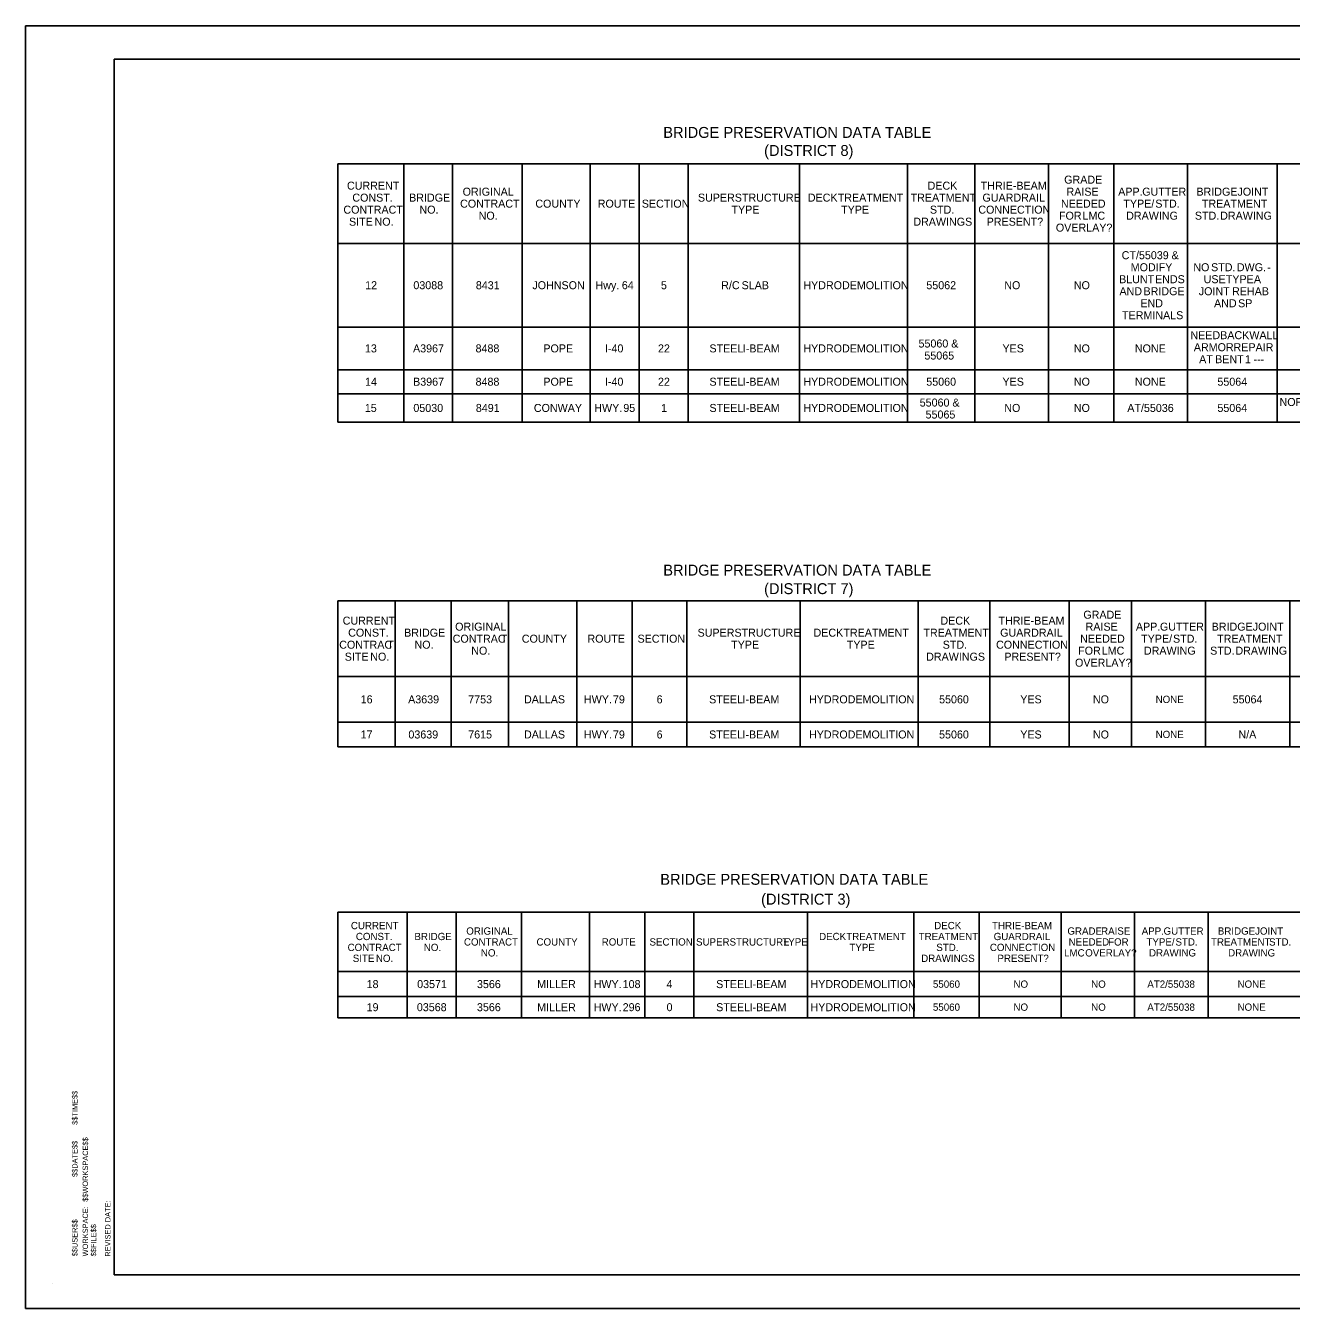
# Model space of a CAD drawing. Extents: x 16 to 1228740, y 11 to 152440.
# Drawn here: x 15.657 to 17.466, y 10.709 to 12.543 of the extents above; entities that cross this region are included whole.
import ezdxf

# ---------------------------------------------------------------- set-up
doc = ezdxf.new("R2010")
doc.units = 0
doc.layers.add('B_Text', color=7, linetype='Continuous')
doc.layers.add('R_Border', color=7, linetype='Continuous')

msp = doc.modelspace()

# ---------------------------------------------------------------- linework, layer by layer
at = {"layer": 'B_Text'}
for p, q in [((16.103, 12.3452), (16.103, 12.3452)), ((16.103, 12.3452), (17.5915, 12.3452)), ((16.103, 11.9761), (16.103, 12.3452)), ((16.1973, 11.9761), (16.1973, 12.3452)), ((16.2672, 11.9761), (16.2672, 12.3452)), ((16.3666, 11.9761), (16.3666, 12.3452)), ((16.4639, 11.9761), (16.4639, 12.3452)), ((16.5339, 11.9761), (16.5339, 12.3452)), ((16.6039, 11.9761), (16.6039, 12.3452)), ((16.7631, 11.9761), (16.7631, 12.3452)), ((16.9172, 11.9761), (16.9172, 12.3452)), ((17.0135, 11.9761), (17.0135, 12.3452)), ((17.119, 11.9761), (17.119, 12.3452)), ((17.2123, 11.9761), (17.2123, 12.3452)), ((17.3177, 11.9761), (17.3177, 12.3452)), ((17.4455, 11.9761), (17.4455, 12.3452)), ((16.103, 12.2316), (17.5915, 12.2316)), ((16.103, 12.112), (17.5915, 12.112)), ((16.103, 12.0511), (17.5915, 12.0511)), ((16.103, 12.0167), (17.5915, 12.0167)), ((16.103, 11.9761), (17.5915, 11.9761)), ((16.103, 11.7209), (16.103, 11.7209)), ((16.103, 11.7209), (17.6037, 11.7209)), ((16.103, 11.512), (16.103, 11.7209)), ((16.1851, 11.512), (16.1851, 11.7209)), ((16.2652, 11.512), (16.2652, 11.7209)), ((16.3473, 11.512), (16.3473, 11.7209)), ((16.4447, 11.512), (16.4447, 11.7209)), ((16.5238, 11.512), (16.5238, 11.7209)), ((16.6018, 11.512), (16.6018, 11.7209)), ((16.7641, 11.512), (16.7641, 11.7209)), ((16.9324, 11.512), (16.9324, 11.7209)), ((17.0348, 11.512), (17.0348, 11.7209)), ((17.1484, 11.512), (17.1484, 11.7209)), ((17.2376, 11.512), (17.2376, 11.7209)), ((17.3431, 11.512), (17.3431, 11.7209)), ((17.4637, 11.512), (17.4637, 11.7209)), ((16.103, 11.6124), (17.6037, 11.6124)), ((16.103, 11.5475), (17.6037, 11.5475)), ((16.103, 11.512), (17.6037, 11.512)), ((16.103, 11.2758), (16.103, 11.2758)), ((16.103, 11.2758), (17.5753, 11.2758)), ((16.103, 11.1247), (16.103, 11.2758)), ((16.2023, 11.1247), (16.2023, 11.2758)), ((16.2723, 11.1247), (16.2723, 11.2758)), ((16.3656, 11.1247), (16.3656, 11.2758)), ((16.4629, 11.1247), (16.4629, 11.2758)), ((16.542, 11.1247), (16.542, 11.2758)), ((16.612, 11.1247), (16.612, 11.2758)), ((16.7742, 11.1247), (16.7742, 11.2758)), ((16.9263, 11.1247), (16.9263, 11.2758)), ((17.0196, 11.1247), (17.0196, 11.2758)), ((17.1372, 11.1247), (17.1372, 11.2758)), ((17.2417, 11.1247), (17.2417, 11.2758)), ((17.3471, 11.1247), (17.3471, 11.2758)), ((16.103, 11.1907), (17.5753, 11.1907)), ((16.103, 11.1552), (17.5753, 11.1552)), ((16.103, 11.1247), (17.5753, 11.1247))]:
    msp.add_line(p, q, dxfattribs=at)
at = {"layer": 'R_Border'}
for p, q in [((15.7833, 12.4948), (18.4422, 12.4948)), ((15.7833, 10.7576), (15.7833, 12.4948)), ((15.6959, 10.7451), (15.6959, 10.7451)), ((18.4422, 10.7576), (15.7833, 10.7576))]:
    msp.add_line(p, q, dxfattribs=at)
msp.add_lwpolyline([(15.6569, 12.5428), (18.4903, 12.5428), (18.4903, 10.7095), (15.6569, 10.7095)], close=True, dxfattribs=at)

# ---------------------------------------------------------------- texts
at = {"layer": 'B_Text'}
for s, height, p in [('BRIDGE PRESERVATION DATA TABLE ', 0.015625, (16.5683, 12.3824)), ('(DISTRICT 8)', 0.015625, (16.7124, 12.3566)), ('CURRENT', 0.01144, (16.1162, 12.3084)), ('DECK', 0.01144, (16.9461, 12.3084)), ('GRADE', 0.01144, (17.1413, 12.317)), ('CONST.', 0.01144, (16.1239, 12.2913)), ('BRIDGE', 0.01144, (16.205, 12.2913)), ('ORIGINAL', 0.01144, (16.2815, 12.2998)), ('SUPERSTRUCTURE', 0.01144, (16.6178, 12.2913)), ('DECK', 0.01144, (16.7749, 12.2913)), (' TREATMENT', 0.01144, (16.8134, 12.2913)), ('TREATMENT', 0.01144, (16.9218, 12.2913)), ('THRIE-BEAM', 0.01144, (17.022, 12.3084)), ('GUARDRAIL', 0.01144, (17.0245, 12.2913)), ('RAISE', 0.01144, (17.1446, 12.2998)), ('APP.', 0.01144, (17.2185, 12.2998)), (' GUTTER', 0.01144, (17.2486, 12.2998)), ('BRIDGE', 0.01144, (17.3303, 12.2998)), (' JOINT', 0.01144, (17.3847, 12.2998)), ('CONTRACT', 0.01144, (16.1111, 12.2741)), ('NO.', 0.01144, (16.2198, 12.2741)), ('CONTRACT', 0.01144, (16.2779, 12.2827)), ('COUNTY', 0.01144, (16.3854, 12.2827)), ('ROUTE', 0.01144, (16.4746, 12.2827)), ('SECTION', 0.01144, (16.5376, 12.2827)), ('TYPE', 0.01144, (16.6658, 12.2741)), ('TYPE', 0.01144, (16.8225, 12.2741)), ('STD.', 0.01144, (16.9494, 12.2741)), ('CONNECTION', 0.01144, (17.0186, 12.2741)), ('NEEDED', 0.01144, (17.1367, 12.2827)), ('TYPE/', 0.01144, (17.2259, 12.2827)), (' STD.', 0.01144, (17.2673, 12.2827)), ('TREATMENT', 0.01144, (17.3381, 12.2827)), ('SITE', 0.01144, (16.1191, 12.2569)), (' NO.', 0.01144, (16.1513, 12.2569)), ('NO.', 0.01144, (16.3044, 12.2655)), ('DRAWINGS', 0.01144, (16.9257, 12.2569)), ('PRESENT?', 0.01144, (17.0305, 12.2569)), ('FOR', 0.01144, (17.1339, 12.2655)), (' LMC', 0.01144, (17.1633, 12.2655)), ('DRAWING', 0.01144, (17.2299, 12.2655)), ('STD.', 0.01144, (17.3281, 12.2655)), (' DRAWING', 0.01144, (17.36, 12.2655)), ('OVERLAY?', 0.01144, (17.1294, 12.2484)), ('CT/55039', 0.01144, (17.2235, 12.209)), (' &', 0.01144, (17.2905, 12.209)), ('MODIFY', 0.01144, (17.2364, 12.1918)), ('NO', 0.01144, (17.3259, 12.1918)), (' STD.', 0.01144, (17.347, 12.1918)), (' DWG.', 0.01144, (17.3838, 12.1918)), (' -', 0.01144, (17.4274, 12.1918)), ('12', 0.01144, (16.1422, 12.1661)), ('03088', 0.01144, (16.2111, 12.1661)), ('8431', 0.01144, (16.3004, 12.1661)), ('JOHNSON', 0.01144, (16.3812, 12.1661)), ('Hwy.', 0.01144, (16.4714, 12.1661)), (' 64', 0.01144, (16.5048, 12.1661)), ('5', 0.0114, (16.565, 12.1661)), ('R/C', 0.01144, (16.6511, 12.1661)), (' SLAB', 0.01144, (16.676, 12.1661)), ('HYDRODEMOLITION', 0.01144, (16.7685, 12.1661)), ('55062', 0.01144, (16.9443, 12.1661)), ('NO', 0.01144, (17.0557, 12.1661)), ('NO', 0.01144, (17.1551, 12.1661)), ('BLUNT', 0.01144, (17.2198, 12.1747)), (' ENDS', 0.01144, (17.2669, 12.1747)), ('USE', 0.01144, (17.3406, 12.1747)), (' TYPE', 0.01144, (17.368, 12.1747)), (' A', 0.01144, (17.4082, 12.1747)), ('AND', 0.01144, (17.2203, 12.1575)), (' BRIDGE', 0.01144, (17.2504, 12.1575)), ('JOINT', 0.01144, (17.3337, 12.1575)), (' REHAB', 0.01144, (17.377, 12.1575)), ('END', 0.01144, (17.2502, 12.1403)), ('AND', 0.01144, (17.3555, 12.1403)), (' SP', 0.01144, (17.3856, 12.1403)), ('TERMINALS', 0.01144, (17.224, 12.1232)), ('NEED', 0.01144, (17.3217, 12.0947)), (' BACKWALL', 0.01144, (17.36, 12.0947)), ('13', 0.01144, (16.1419, 12.0758)), ('A3967', 0.01144, (16.2106, 12.0758)), ('8488', 0.01144, (16.3, 12.0758)), ('POPE', 0.01144, (16.3969, 12.0758)), ('I-40', 0.01144, (16.4849, 12.0758)), ('22', 0.01144, (16.5607, 12.0758)), ('STEEL', 0.01144, (16.6343, 12.0758)), (' I-BEAM', 0.01144, (16.6777, 12.0758)), ('HYDRODEMOLITION', 0.01144, (16.7685, 12.0758)), ('55060 &', 0.01144, (16.9331, 12.0828)), ('YES', 0.01144, (17.0531, 12.0758)), ('NO', 0.01144, (17.1551, 12.0758)), ('NONE', 0.01144, (17.2423, 12.0758)), ('ARMOR', 0.01144, (17.3266, 12.0775)), (' REPAIR', 0.01144, (17.3791, 12.0775)), ('55065', 0.01144, (16.9415, 12.0656)), ('AT', 0.01144, (17.3342, 12.0604)), (' BENT', 0.01144, (17.3528, 12.0604)), (' 1', 0.01144, (17.3955, 12.0604)), (' ---', 0.01144, (17.4077, 12.0604)), ('14', 0.01144, (16.142, 12.0282)), ('B3967', 0.01144, (16.2107, 12.0282)), ('8488', 0.01144, (16.3, 12.0282)), ('POPE', 0.01144, (16.3969, 12.0282)), ('I-40', 0.01144, (16.4849, 12.0282)), ('22', 0.01144, (16.5607, 12.0282)), ('STEEL', 0.01144, (16.6343, 12.0282)), (' I-BEAM', 0.01144, (16.6777, 12.0282)), ('HYDRODEMOLITION', 0.01144, (16.7685, 12.0282)), ('55060', 0.01144, (16.9442, 12.0282)), ('YES', 0.01144, (17.0531, 12.0282)), ('NO', 0.01144, (17.1551, 12.0282)), ('NONE', 0.01144, (17.2423, 12.0282)), ('55064', 0.01144, (17.3603, 12.0282)), ('55060 &', 0.01144, (16.9348, 11.9984)), ('NORTH', 0.01144, (17.4491, 11.9992)), ('15', 0.01144, (16.1417, 11.9907)), ('05030', 0.01144, (16.2111, 11.9907)), ('8491', 0.01144, (16.3004, 11.9907)), ('CONWAY', 0.01144, (16.3833, 11.9907)), ('HWY.', 0.01144, (16.4697, 11.9907)), (' 95', 0.01144, (16.5069, 11.9907)), ('1', 0.0114, (16.5652, 11.9907)), ('STEEL', 0.01144, (16.6343, 11.9907)), (' I-BEAM', 0.01144, (16.6777, 11.9907)), ('HYDRODEMOLITION', 0.01144, (16.7685, 11.9907)), ('55065', 0.01144, (16.9432, 11.9813)), ('NO', 0.01144, (17.0557, 11.9907)), ('NO', 0.01144, (17.1551, 11.9907)), ('AT/55036', 0.01144, (17.2315, 11.9907)), ('55064', 0.01144, (17.3603, 11.9907)), ('BRIDGE PRESERVATION DATA TABLE ', 0.015625, (16.5683, 11.7568)), ('(DISTRICT 7)', 0.015625, (16.7124, 11.7303)), ('CURRENT', 0.01144, (16.1101, 11.6867)), ('DECK', 0.01144, (16.9644, 11.6867)), ('THRIE-BEAM', 0.01144, (17.0474, 11.6867)), ('GRADE', 0.01144, (17.1687, 11.6952)), ('CONST.', 0.01144, (16.1179, 11.6695)), ('BRIDGE', 0.01144, (16.1979, 11.6695)), ('ORIGINAL', 0.01144, (16.2708, 11.6781)), ('SUPERSTRUCTURE', 0.01144, (16.6173, 11.6695)), ('DECK', 0.01144, (16.783, 11.6695)), (' TREATMENT', 0.01144, (16.8215, 11.6695)), ('TREATMENT', 0.01144, (16.9401, 11.6695)), ('GUARDRAIL', 0.01144, (17.0498, 11.6695)), ('RAISE', 0.01144, (17.1719, 11.6781)), ('APP.', 0.01144, (17.2438, 11.6781)), (' GUTTER', 0.01144, (17.2739, 11.6781)), ('BRIDGE', 0.01144, (17.3521, 11.6781)), (' JOINT', 0.01144, (17.4065, 11.6781)), ('CONTRAC', 0.01144, (16.1051, 11.6523)), ('T', 0.0114, (16.1738, 11.6523)), ('NO.', 0.01144, (16.2127, 11.6523)), ('CONTRAC', 0.01144, (16.2673, 11.6609)), ('T', 0.0114, (16.336, 11.6609)), ('COUNTY', 0.01144, (16.3661, 11.6609)), ('ROUTE', 0.01144, (16.4599, 11.6609)), ('SECTION', 0.01144, (16.5315, 11.6609)), ('TYPE', 0.01144, (16.6653, 11.6523)), ('TYPE', 0.01144, (16.8306, 11.6523)), ('STD.', 0.01144, (16.9677, 11.6523)), ('CONNECTION', 0.01144, (17.0439, 11.6523)), ('NEEDED', 0.01144, (17.1641, 11.6609)), ('TYPE/', 0.01144, (17.2513, 11.6609)), (' STD.', 0.01144, (17.2926, 11.6609)), ('TREATMENT', 0.01144, (17.3599, 11.6609)), ('SITE', 0.01144, (16.113, 11.6352)), (' NO.', 0.01144, (16.1452, 11.6352)), ('NO.', 0.01144, (16.2938, 11.6438)), ('DRAWINGS', 0.01144, (16.944, 11.6352)), ('PRESENT?', 0.01144, (17.0558, 11.6352)), ('FOR', 0.01144, (17.1613, 11.6438)), (' LMC', 0.01144, (17.1907, 11.6438)), ('DRAWING', 0.01144, (17.2553, 11.6438)), ('STD.', 0.01144, (17.3499, 11.6438)), (' DRAWING', 0.01144, (17.3818, 11.6438)), ('OVERLAY?', 0.01144, (17.1568, 11.6266)), ('16', 0.01144, (16.1358, 11.5742)), ('A3639', 0.01144, (16.2036, 11.5742)), ('7753', 0.01144, (16.2895, 11.5742)), ('DALLAS', 0.01144, (16.3692, 11.5742)), ('HWY.', 0.01144, (16.4549, 11.5742)), (' 79', 0.01144, (16.4921, 11.5742)), ('6', 0.0114, (16.5588, 11.5742)), ('STEEL', 0.01144, (16.6338, 11.5742)), (' I-BEAM', 0.01144, (16.6772, 11.5742)), ('HYDRODEMOLITION', 0.01144, (16.7766, 11.5742)), ('55060', 0.01144, (16.9625, 11.5742)), ('YES', 0.01144, (17.0785, 11.5742)), ('NO', 0.01144, (17.1824, 11.5742)), ('NONE', 0.0104, (17.272, 11.5747)), ('55064', 0.01144, (17.3821, 11.5742)), ('17', 0.01144, (16.1357, 11.524)), ('03639', 0.01144, (16.204, 11.524)), ('7615', 0.01144, (16.2895, 11.524)), ('DALLAS', 0.01144, (16.3692, 11.524)), ('HWY.', 0.01144, (16.4549, 11.524)), (' 79', 0.01144, (16.4921, 11.524)), ('6', 0.0114, (16.5588, 11.524)), ('STEEL', 0.01144, (16.6338, 11.524)), (' I-BEAM', 0.01144, (16.6772, 11.524)), ('HYDRODEMOLITION', 0.01144, (16.7766, 11.524)), ('55060', 0.01144, (16.9625, 11.524)), ('YES', 0.01144, (17.0785, 11.524)), ('NO', 0.01144, (17.1824, 11.524)), ('NONE', 0.0104, (17.272, 11.5246)), ('N/A', 0.01144, (17.3904, 11.524)), ('BRIDGE PRESERVATION DATA TABLE ', 0.015625, (16.564, 11.3149)), ('(DISTRICT 3)', 0.015625, (16.7081, 11.2865)), ('CURRENT', 0.0104, (16.1218, 11.2514)), ('DECK', 0.0104, (16.9555, 11.2514)), ('THRIE-BEAM', 0.0104, (17.0382, 11.2514)), ('CONST.', 0.0104, (16.1289, 11.2358)), ('BRIDGE', 0.0104, (16.2126, 11.2358)), ('CONTRACT', 0.0104, (16.2834, 11.228)), ('ORIGINAL', 0.0104, (16.2867, 11.2436)), ('COUNTY', 0.0104, (16.3871, 11.228)), ('ROUTE', 0.0104, (16.4803, 11.228)), ('SECTION', 0.0104, (16.5486, 11.228)), ('SUPERSTRUCTURE', 0.0104, (16.6151, 11.228)), (' TYPE', 0.0104, (16.7346, 11.228)), ('DECK', 0.0104, (16.791, 11.2358)), (' TREATMENT', 0.0104, (16.826, 11.2358)), ('TREATMENT', 0.0104, (16.9334, 11.2358)), ('GUARDRAIL', 0.0104, (17.0405, 11.2358)), ('GRADE', 0.0104, (17.1459, 11.2436)), ('NEEDED', 0.0104, (17.1476, 11.228)), (' RAISE', 0.0104, (17.1902, 11.2436)), (' FOR', 0.0104, (17.2002, 11.228)), ('APP.', 0.0104, (17.2521, 11.2436)), ('TYPE/', 0.0104, (17.2589, 11.228)), (' GUTTER', 0.0104, (17.2795, 11.2436)), (' STD.', 0.0104, (17.2965, 11.228)), ('TREATMENT', 0.0104, (17.3512, 11.228)), ('BRIDGE', 0.0104, (17.3609, 11.2436)), (' JOINT', 0.0104, (17.4103, 11.2436)), (' STD.', 0.0104, (17.4303, 11.228)), ('CONTRACT', 0.0104, (16.1171, 11.2202)), ('NO.', 0.0104, (16.226, 11.2202)), ('NO.', 0.0104, (16.3076, 11.2124)), ('TYPE', 0.0104, (16.8343, 11.2202)), ('STD.', 0.0104, (16.9585, 11.2202)), ('CONNECTION', 0.0104, (17.0351, 11.2202)), ('LMC', 0.0104, (17.1411, 11.2124)), (' OVERLAY?', 0.0104, (17.1675, 11.2124)), ('DRAWING', 0.0104, (17.2625, 11.2124)), ('DRAWING', 0.0104, (17.3756, 11.2124)), ('SITE', 0.0104, (16.1245, 11.2046)), (' NO.', 0.0104, (16.1537, 11.2046)), ('DRAWINGS', 0.0104, (16.9369, 11.2046)), ('PRESENT?', 0.0104, (17.0459, 11.2046)), ('18', 0.01144, (16.1443, 11.1672)), ('03571', 0.01144, (16.2165, 11.1672)), ('3566', 0.01144, (16.302, 11.1672)), ('MILLER', 0.01144, (16.388, 11.1672)), ('HWY.', 0.01144, (16.4688, 11.1672)), (' 108', 0.01144, (16.506, 11.1672)), ('4', 0.0114, (16.5729, 11.1672)), ('STEEL', 0.01144, (16.6439, 11.1672)), (' I-BEAM', 0.01144, (16.6873, 11.1672)), ('HYDRODEMOLITION', 0.01144, (16.7787, 11.1672)), ('55060', 0.0104, (16.9537, 11.1677)), ('NO', 0.0104, (17.0688, 11.1677)), ('NO', 0.0104, (17.1799, 11.1677)), ('AT2/55038', 0.0104, (17.2601, 11.1677)), ('NONE', 0.0104, (17.3891, 11.1677)), ('19', 0.01144, (16.1443, 11.1342)), ('03568', 0.01144, (16.2161, 11.1342)), ('3566', 0.01144, (16.302, 11.1342)), ('MILLER', 0.01144, (16.388, 11.1342)), ('HWY.', 0.01144, (16.4688, 11.1342)), (' 296', 0.01144, (16.506, 11.1342)), ('0', 0.0114, (16.573, 11.1342)), ('STEEL', 0.01144, (16.6439, 11.1342)), (' I-BEAM', 0.01144, (16.6873, 11.1342)), ('HYDRODEMOLITION', 0.01144, (16.7787, 11.1342)), ('55060', 0.0104, (16.9537, 11.1348)), ('NO', 0.0104, (17.0688, 11.1348)), ('NO', 0.0104, (17.1799, 11.1348)), ('AT2/55038', 0.0104, (17.2601, 11.1348)), ('NONE', 0.0104, (17.3891, 11.1348))]:
    msp.add_text(s, height=height, dxfattribs=at).set_placement(p)
at = {"layer": 'R_Border'}
for s, p in [('$$TIME$$', (15.7311, 10.9718)), ('$$DATE$$', (15.7311, 10.8973)), ('$$WORKSPACE$$', (15.746, 10.8618)), ('REVISED DATE:', (15.7782, 10.7833)), ('WORKSPACE:', (15.746, 10.7838)), ('$$USER$$', (15.7311, 10.7839)), ('$$FILE$$', (15.7578, 10.7839))]:
    msp.add_text(s, height=0.00765, rotation=90, dxfattribs=at).set_placement(p)

doc.saveas('drawing.dxf')
